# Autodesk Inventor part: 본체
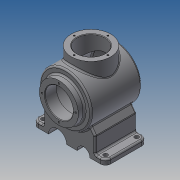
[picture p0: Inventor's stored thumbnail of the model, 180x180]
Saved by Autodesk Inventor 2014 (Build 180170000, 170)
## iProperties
Created: 2018-08
Part Number: 본체
Material: Generic
Document SubType Name: Modeling
Designer: kb542
Density: 1 g/cm^3
Appearance: Default
Author: kb542
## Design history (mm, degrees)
sketch "스케치1"
  geometry: L1 (-60, 0)-(60, 0); L2 (-60, 27)-(-60, 37.5); L3 (-60, 37.5)-(-48, 37.5); L4 (-48, 37.5)-(-48, 50); L5 (-60, 27)-(-38, 27); L6 (-38, 27)-(-38, 40); L7 (-38, 40)-(42.163, 40); L8 (-48, 50)-(48.671, 50); A1 r 116 centre (-56, 0) between (60, 0) and (48.671, 50); A2 r 106 centre (-56, 0) between (50, 0) and (42.163, 40); 3 further points
  constraints: 16 end point, 4 point on circle, 3 perpendicular, 2 centre point, 2 midpoint, 2 parallel, 2 point on line, 1 coincident, 1 horizontal, 1 vertical alignment
  dimensions: "d2" = 54 diameter of L5 L1; "d3" = 75 diameter of L3 L1; "d7" = 12 distance of L2.end L3.end; "d9" = 22 distance of L2.start L5.end; "d10" = 80 diameter of L7 L1; "d11" = 116 radius of A1; "d13" = 108 distance from line of L1.end L4; "d14" = 10 radial gap between concentric circles of A1 A2; "d15" = 100 diameter of L8 L1
revolve "회전1" sketch "스케치1" stored, may be unused: angle "d16" = 90 deg
node "작업 평면1"
sketch "스케치2"
  geometry: L1 (-41.103, -28.471)-(-50, -41.178); L2 (-50, -41.178)-(-50, -72); L3 (-50, -72)-(-70, -72); L4 (-70, -72)-(-70, -82); L5 (-70, -82)-(70, -82); L6 (70, -82)-(70, -72); L7 (70, -72)-(50, -72); L8 (50, -72)-(50, -41.178); L9 (50, -41.178)-(41.103, -28.471); A1 r 50 centre (0, 0) between (-41.103, -28.471) and (41.103, -28.471) reference; 2 further points
  constraints: 18 end point, 6 perpendicular, 2 horizontal alignment, 2 point on circle, 1 midpoint, 1 parallel, 1 vertical, 1 vertical alignment
  dimensions: "d18" = 82 distance from line of L5 point (0, 0); "d19" = 140 distance between parallel lines of L6 L4; "d22" = 35 deg angle of L9 L6; "d23" = 10 distance of L3.end L4.end; "d24" = 20 distance of L2.end L3.end; "d25" = 20 distance of L6.end L7.end; "d26" = 35 deg angle of L1 L4
extrude "돌출1" join sketch "스케치2" distance "d27" = 80; taper "d28" = 0 deg
sketch "스케치3"
  geometry: L1 (-70, -82)-(70, -82) reference; L2 (0, 0)-(0, -82); L3 (70, -82)-(-70, -82) reference; C1 r 17.5 at (-22.5, -82); C2 r 12.5 at (27.5, -82); A1 r 50 centre (0, 0) between (-41.103, -28.471) and (41.103, -28.471) reference
  constraints: 2 centre point, 2 end point, 2 point on line, 1 midpoint
  dimensions: "d29" = 22.5 distance of C1.centre L2.end; "d30" = 27.5 distance of C2.centre L2.end; "d31" = 12.5 radius of C2; "d32" = 17.5 radius of C1
extrude "돌출2" cut sketch "스케치3" stored distance "d33" = 80; taper "d34" = 0 deg
node "작업 평면2"
sketch "스케치5"
  geometry: L1 (-88, -120)-(-88, -20) reference; C1 r 38 at (-38, -70); 1 further point
  constraints: 1 centre point, 1 horizontal alignment
  dimensions: "d36" = 50 distance from line of C1.centre L1; "d37" = 76 diameter of C1
extrude "돌출3" join sketch "스케치5" stored distance "d38" = 80; taper "d39" = 0 deg
sketch "스케치6"
  geometry: C1 r 38 at (0, 0) reference; C2 r 27 at (0, 0); 1 further point
  constraints: 1 centre point, 1 coincident
  dimensions: "d40" = 54 diameter of C2
extrude "돌출4" cut sketch "스케치6" stored distance "d41" = 80; taper "d42" = 0 deg
node "작업 평면3"
fillet "모깎기1" dims "d47" = 10
fillet "모깎기2" dims "d48" = 3
chamfer "모따기1" distance "d49" = 1; stored, may be unused: second distance "d50" = 2, angle "d51" = 45 deg
sketch "스케치8"
  geometry: C1 r 38 at (0, 0) reference; 2 further points
  constraints: 1 vertical alignment
  dimensions: "d52" = 32.5 distance of C1.centre point (0, 32.5)
hole "구멍1" sketch "스케치8" at (0, 32.5) diameter "d53" = 3.242; stored, may be unused: countersink angle "d57" = 90 deg, drill point angle "d59" = 118 deg; dims "d54" = 8, "d55" = 4, "d56" = 2, "d58" = 10
sketch "스케치9"
  geometry: C1 r 37.5 at (0, 0) reference; 1 further point
  constraints: 1 vertical alignment
  dimensions: "d63" = 32.5 distance of C1.centre point (0, 32.5)
hole "구멍2" sketch "스케치9" at (0, 32.5) diameter "d64" = 3.242; stored, may be unused: countersink angle "d68" = 90 deg, drill point angle "d70" = 118 deg; dims "d65" = 8, "d66" = 4, "d67" = 2, "d69" = 10
fillet "모깎기3" dims "d74" = 3
fillet "모깎기4" dims "d75" = 3
fillet "모깎기5" dims "d76" = 3
node "작업 평면4"
sketch "스케치11"
  geometry: C1 r 32.5 at (0, 0); 1 further point
  constraints: 1 centre point, 1 coincident, 1 other
  dimensions: "d77" = 65 diameter of C1
feature "엠보싱2" sketch "스케치11" dims "d2" = 54, "d3" = 75, "d7" = 12, "d9" = 22, "d10" = 80, "d11" = 116, "d13" = 108, "d14" = 10, "d15" = 100, "d18" = 82, "d19" = 140, "d22" = 35 deg, "d23" = 10, "d24" = 20, "d25" = 20, "d26" = 35 deg, "d78" = 0.5, "d79" = 0
hole "구멍3" diameter "d82" = 8; stored, may be unused: countersink angle "d86" = 90 deg, drill point angle "d88" = 118 deg; dims "d80" = 10, "d81" = 10, "d83" = 8, "d84" = 4, "d85" = 2, "d87" = 10
hole "구멍4" diameter "d91" = 8; stored, may be unused: countersink angle "d95" = 90 deg, drill point angle "d97" = 118 deg; dims "d89" = 10, "d90" = 10, "d92" = 8, "d93" = 4, "d94" = 2, "d96" = 10
hole "구멍5" diameter "d100" = 8; stored, may be unused: countersink angle "d104" = 90 deg, drill point angle "d106" = 118 deg; dims "d98" = 10, "d99" = 10, "d101" = 8, "d102" = 4, "d103" = 2, "d105" = 10
hole "구멍6" diameter "d109" = 8; stored, may be unused: countersink angle "d113" = 90 deg, drill point angle "d115" = 118 deg; dims "d107" = 10, "d108" = 10, "d110" = 8, "d111" = 4, "d112" = 2, "d114" = 10
node "솔리드1"
pattern_circular "원형 패턴1" dims angle "d61" = 360 deg
pattern_circular "원형 패턴2" dims angle "d72" = 360 deg
other parameters: "d17" = -8, "d35" = -147, "d43" = -54
